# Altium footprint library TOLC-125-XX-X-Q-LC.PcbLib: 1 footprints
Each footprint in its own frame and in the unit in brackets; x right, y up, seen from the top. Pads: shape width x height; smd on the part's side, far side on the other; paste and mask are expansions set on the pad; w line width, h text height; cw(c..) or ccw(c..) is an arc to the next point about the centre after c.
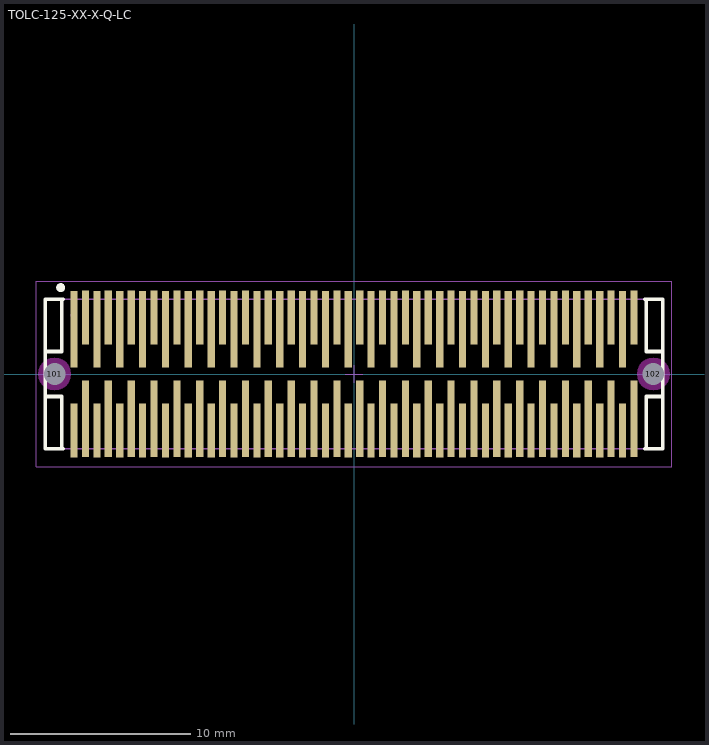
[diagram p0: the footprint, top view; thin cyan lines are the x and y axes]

## TOLC-125-XX-X-Q-LC [mm] "1.27mm pitch, 100 pin, terminal strip; 4 rows, w/locking clips, SMT"
height 5.59
pads (102):
  rect 0.4x4.25 smd mask+0: 1(-15.557,2.5) 4(-14.922,-2.5) 5(-14.287,2.5) 8(-13.652,-2.5) 9(-13.018,2.5) 12(-12.383,-2.5) 13(-11.747,2.5) 16(-11.112,-2.5) 17(-10.477,2.5) 20(-9.842,-2.5) 21(-9.207,2.5) 24(-8.572,-2.5) 25(-7.938,2.5) 28(-7.302,-2.5) 29(-6.667,2.5) 32(-6.032,-2.5) 33(-5.397,2.5) 36(-4.763,-2.5) 37(-4.127,2.5) 40(-3.492,-2.5) 41(-2.857,2.5) 44(-2.222,-2.5) 45(-1.587,2.5) 48(-0.953,-2.5) 49(-0.318,2.5) 52(0.318,-2.5) 53(0.953,2.5) 56(1.587,-2.5) 57(2.222,2.5) 60(2.857,-2.5) 61(3.492,2.5) 64(4.127,-2.5) 65(4.763,2.5) 68(5.397,-2.5) 69(6.032,2.5) 72(6.667,-2.5) 73(7.302,2.5) 76(7.938,-2.5) 77(8.572,2.5) 80(9.207,-2.5) 81(9.842,2.5) 84(10.477,-2.5) 85(11.112,2.5) 88(11.747,-2.5) 89(12.383,2.5) 92(13.018,-2.5) 93(13.652,2.5) 96(14.287,-2.5) 97(14.922,2.5) 100(15.557,-2.5)
  rect 0.4x3 smd mask+0: 2(-15.557,-3.135) 3(-14.922,3.135) 6(-14.287,-3.135) 7(-13.652,3.135) 10(-13.018,-3.135) 11(-12.383,3.135) 14(-11.747,-3.135) 15(-11.112,3.135) 18(-10.477,-3.135) 19(-9.842,3.135) 22(-9.207,-3.135) 23(-8.572,3.135) 26(-7.938,-3.135) 27(-7.302,3.135) 30(-6.667,-3.135) 31(-6.032,3.135) 34(-5.397,-3.135) 35(-4.763,3.135) 38(-4.127,-3.135) 39(-3.492,3.135) 42(-2.857,-3.135) 43(-2.222,3.135) 46(-1.587,-3.135) 47(-0.953,3.135) 50(-0.318,-3.135) 51(0.318,3.135) 54(0.953,-3.135) 55(1.587,3.135) 58(2.222,-3.135) 59(2.857,3.135) 62(3.492,-3.135) 63(4.127,3.135) 66(4.763,-3.135) 67(5.397,3.135) 70(6.032,-3.135) 71(6.667,3.135) 74(7.302,-3.135) 75(7.938,3.135) 78(8.572,-3.135) 79(9.207,3.135) 82(9.842,-3.135) 83(10.477,3.135) 86(11.112,-3.135) 87(11.747,3.135) 90(12.383,-3.135) 91(13.018,3.135) 94(13.652,-3.135) 95(14.287,3.135) 98(14.922,-3.135) 99(15.557,3.135)
  round 1 hole 1.2 unplated mask+0: 101(-16.637,0) 102(16.637,0)
Top Overlay:
  circle w0.25: c-16.3,4.8 r0.125
  lines w0.2: -17.15,-1.25 -16.25,-1.25 -16.25,-4.15 ; -17.15,1.25 -16.25,1.25 -16.25,4.15 ; -16.15,-4.15 -17.15,-4.15 -17.15,4.15 -16.15,4.15 ; 16.15,-4.15 17.15,-4.15 17.15,4.15 16.15,4.15 ; 16.25,-4.15 16.25,-1.25 17.15,-1.25 ; 16.25,4.15 16.25,1.25 17.15,1.25
Keep-Out Layer:
  pour cut-out: 17.545,0 17.514,0.235 17.423,0.454 17.279,0.642 17.091,0.786 16.872,0.877 16.637,0.908 16.402,0.877 16.183,0.786 15.995,0.642 15.851,0.454 15.76,0.235 15.729,0 15.76,-0.235 15.851,-0.454 15.995,-0.642 16.183,-0.786 16.402,-0.877 16.637,-0.908 16.872,-0.877 17.091,-0.786 17.279,-0.642 17.423,-0.454 17.514,-0.235
  pour cut-out: -15.729,0 -15.76,0.235 -15.851,0.454 -15.995,0.642 -16.183,0.786 -16.402,0.877 -16.637,0.908 -16.872,0.877 -17.091,0.786 -17.279,0.642 -17.423,0.454 -17.514,0.235 -17.545,0 -17.514,-0.235 -17.423,-0.454 -17.279,-0.642 -17.091,-0.786 -16.872,-0.877 -16.637,-0.908 -16.402,-0.877 -16.183,-0.786 -15.995,-0.642 -15.851,-0.454 -15.76,-0.235
Mechanical 12:
  lines w0.001: -17.15,-4.15 17.15,-4.15 17.15,4.15 -17.15,4.15 -17.15,-4.15 ; -17.15,-1.25 -17.15,1.25 -16.25,1.25 -16.25,4.15 16.25,4.15 16.25,1.25 17.15,1.25 17.15,-1.25 16.25,-1.25 16.25,-4.15 -16.25,-4.15 -16.25,-1.25 -17.15,-1.25
Mechanical 13:
  circle w0.1: c-15.574,3.265 r0.127
  lines w0.1: -17.15,-4.15 17.15,-4.15 17.15,4.15 -17.15,4.15 -17.15,-4.15 ; -17.15,-1.25 -17.15,1.25 -16.25,1.25 -16.25,4.15 16.25,4.15 16.25,1.25 17.15,1.25 17.15,-1.25 16.25,-1.25 16.25,-4.15 -16.25,-4.15 -16.25,-1.25 -17.15,-1.25
  text ".Designator" at 0,-0.127 h1.52
Mechanical 15:
  lines w0.05: -0.5,0 0.5,0 ; 0,-0.5 0,0.5 ; -17.653,-5.15 -17.653,5.15 17.653,5.15 17.653,-5.15 -17.653,-5.15
Mechanical 16:
  circle w0.001: c-15.574,3.265 r0.127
